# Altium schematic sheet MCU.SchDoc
size A
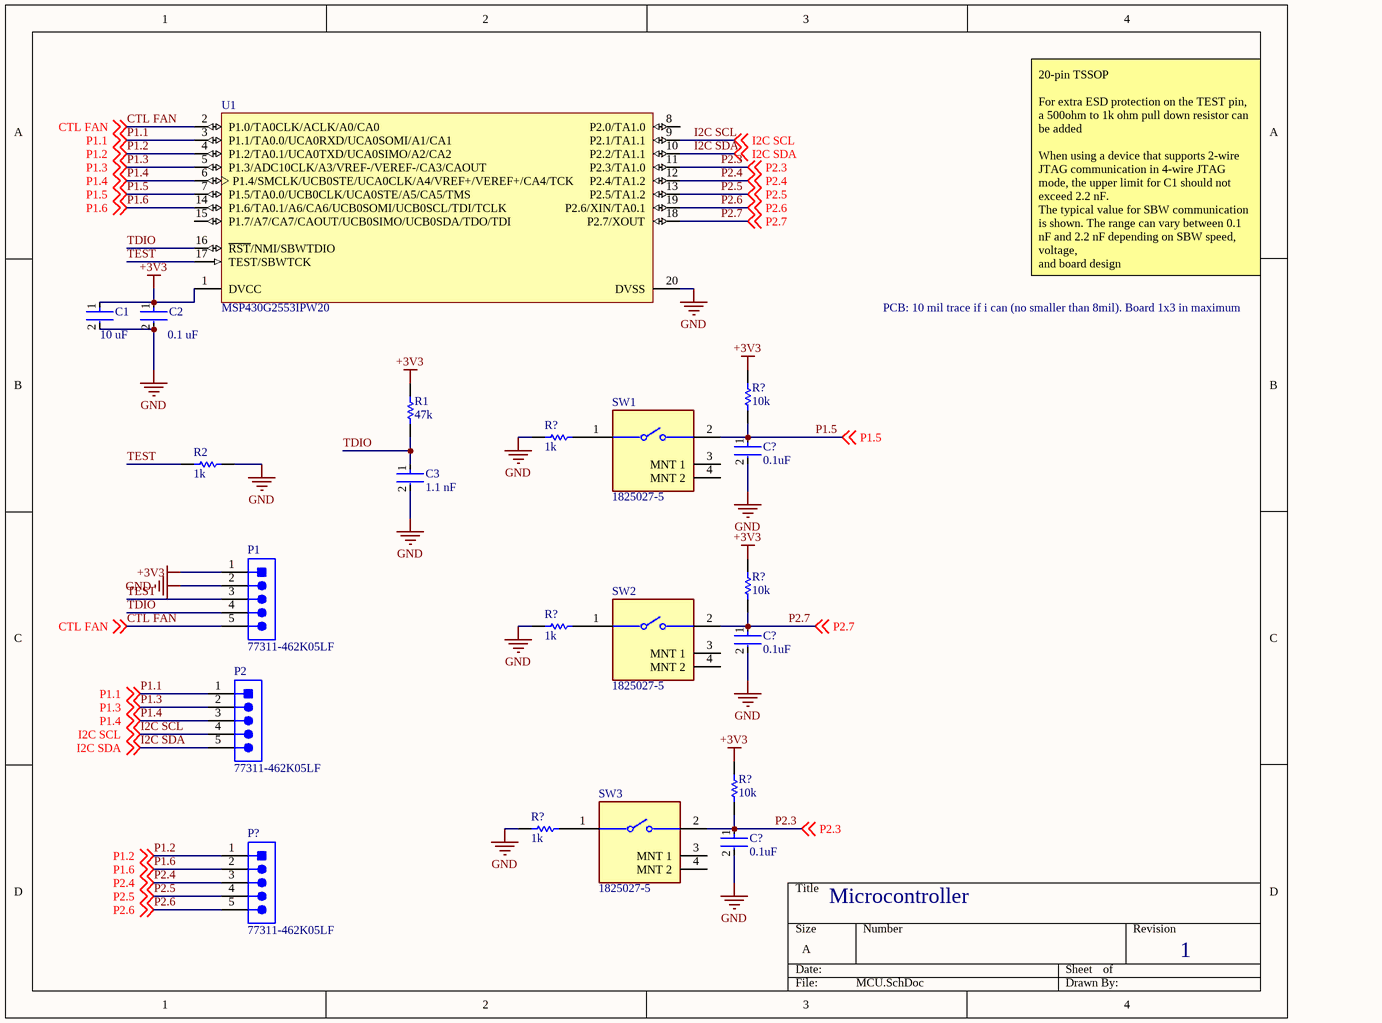
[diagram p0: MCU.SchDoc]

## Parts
(Parts that share a designator on the sheet are numbered #1, #2 ... from top to bottom, then left to right.)
C1  10 uF  [FP-C0805C-DG-MFG]
C2  0.1 uF  [FP-C0805C-DG-MFG]
C3  1.1 nF  [FP-C0805C-DG-MFG]
C?#1  0.1uF  [FP-C0805C-DG-MFG]
C?#2  0.1uF  [FP-C0805C-DG-MFG]
C?#3  0.1uF  [FP-C0805C-DG-MFG]
P1  77311-462K05LF  [FCI-77311-5_V]
P2  77311-462K05LF  [FCI-77311-5_V]
P?  77311-462K05LF  [FCI-77311-5_V]
R1  47k  [RESC2013X50X30LL20T20]
R2  1k  [RESC2013X50X30LL20T20]
R?#1  value 10k  [RESC2013X70X40ML20T20]  (hidden comment: Resistor 1k +/-1% 0805 125 mW)
R?#2  value 1k  [RESC2013X70X40ML20T20]  (hidden comment: Resistor 1k +/-1% 0805 125 mW)
R?#3  value 10k  [RESC2013X70X40ML20T20]  (hidden comment: Resistor 1k +/-1% 0805 125 mW)
R?#4  value 1k  [RESC2013X70X40ML20T20]  (hidden comment: Resistor 1k +/-1% 0805 125 mW)
R?#5  value 10k  [RESC2013X70X40ML20T20]  (hidden comment: Resistor 1k +/-1% 0805 125 mW)
R?#6  value 1k  [RESC2013X70X40ML20T20]  (hidden comment: Resistor 1k +/-1% 0805 125 mW)
SW1  1825027-5  [FP-1825027-5-0]
SW2  1825027-5  [FP-1825027-5-0]
SW3  1825027-5  [FP-1825027-5-0]
U1  MSP430G2553IPW20  [PW0020A_L]

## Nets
+3V3: C1.1 C2.1 P1.1(DTR) R1.2 R?#1.1 R?#3.1 R?#5.1 U1.1(DVCC)
GND: C1.2 C2.2 C3.2 C?#1.2 C?#2.2 C?#3.2 P1.2(RXI) R2.2 R?#2.2 R?#4.2 R?#6.2 U1.20(DVSS)
CTL FAN: P1.5(CTS) U1.2(P1.0/TA0CLK/ACLK/A0/CA0) ; off-sheet CTL FAN
I2C SCL: P2.4(VCC) U1.9(P2.1/TA1.1) ; off-sheet I2C SCL
I2C SDA: P2.5(CTS) U1.10(P2.2/TA1.1) ; off-sheet I2C SDA
P1.1: P2.1(DTR) U1.3(P1.1/TA0.0/UCA0RXD/UCA0SOMI/A1/CA1) ; off-sheet P1.1
P1.2: P?.1(DTR) U1.4(P1.2/TA0.1/UCA0TXD/UCA0SIMO/A2/CA2) ; off-sheet P1.2
P1.3: P2.2(RXI) U1.5(P1.3/ADC10CLK/A3/VREF-/VEREF-/CA3/CAOUT) ; off-sheet P1.3
P1.4: P2.3(TXO) U1.6(P1.4/SMCLK/UCB0STE/UCA0CLK/A4/VREF+/VEREF+/CA4/TCK) ; off-sheet P1.4
P1.5: C?#1.1 R?#1.2 SW1.2 U1.7(P1.5/TA0.0/UCB0CLK/UCA0STE/A5/CA5/TMS) ; off-sheet P1.5
P1.6: P?.2(RXI) U1.14(P1.6/TA0.1/A6/CA6/UCB0SOMI/UCB0SCL/TDI/TCLK) ; off-sheet P1.6
P2.3: C?#3.1 R?#5.2 SW3.2 U1.11(P2.3/TA1.0) ; off-sheet P2.3
P2.4: P?.3(TXO) U1.12(P2.4/TA1.2) ; off-sheet P2.4
P2.5: P?.4(VCC) U1.13(P2.5/TA1.2) ; off-sheet P2.5
P2.6: P?.5(CTS) U1.19(P2.6/XIN/TA0.1) ; off-sheet P2.6
P2.7: C?#2.1 R?#3.2 SW2.2 U1.18(P2.7/XOUT) ; off-sheet P2.7
TDIO: C3.1 P1.4(VCC) R1.1 U1.16(~{RST}/NMI/SBWTDIO)
TEST: P1.3(TXO) R2.1 U1.17(TEST/SBWTCK)
NetR?#2_1: R?#2.1 SW1.1
NetR?#4_1: R?#4.1 SW2.1
NetR?#6_1: R?#6.1 SW3.1

Not connected (* = marked no-connect by the designer): SW1 3(MNT_1) 4(MNT_2); SW2 3(MNT_1) 4(MNT_2); SW3 3(MNT_1) 4(MNT_2); U1 8(P2.0/TA1.0) 15(P1.7/A7/CA7/CAOUT/UCB0SIMO/UCB0SDA/TDO/TDI)

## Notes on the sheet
- 20-pin TSSOP
  For extra ESD protection on the TEST pin, a 500ohm to 1k ohm pull down resistor can be added
  When using a device that supports 2-wire JTAG communication in 4-wire JTAG mode, the upper limit for C1 should not exceed 2.2 nF.
  The typical value for SBW communication is shown. The range can vary between 0.1 nF and 2.2 nF depending on SBW speed, voltage,
  and board design
- PCB: 10 mil trace if i can (no smaller than 8mil). Board 1x3 in maximum
- Microcontroller
- 1

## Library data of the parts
C1-C3 C?#1-C?#3 = CMP-2007-03243-2: CAP CER 10UF 10V X5R 0805; Manufacturer Part Number: C0805C106K8PACTU; Manufacturer: Kemet; 3DS Part Number: 220-00001; Tolerance: 10%; Temperature Coefficient: 15%; Material: Ceramic
P1 P2 P? = CMP-1698-00006-1: Male Header, Pitch 2.54 mm, 1 x 5 Position, Height 16.24 mm, Tail Length 3.05 mm, / -65 to 125 degC, RoHS, Tape and Reel; Shielding: Shielded; Current Rating: 1 A; Gender: Female
R1 R2 = CMP-2001-04896-1: Manufacturer: Vishay Dale; Part Number: CRCW08050000Z0EA
R?#1-R?#6 = CMP-009-00010-4: Chip Resistor, 1 KOhm, +/- 1%, 0.125 W, -55 to 155 degC, 0805 (2013 Metric); Power: 125mW; Voltage Rating: 150V
SW1-SW3 = CMP-2000-05514-2: SWITCH TACTILE SPST-NO 0.05A 24V; Manufacturer: TE Connectivity; Contact Current Rating: 50mA; Contact Resistance: 100mΩ; Electromechanical Life: 100000Cycles; Operating Force: 160gf
U1 = CMP-0365-00585-2: 16 MHz Mixed Signal Microcontroller with 16 KB Flash, 512 B SRAM and 24 GPIOs, -40 to 85 degC, 20-pin SOP (PW), Green (RoHS & no Sb/Br); Manufacturer: Texas Instruments; Timers - 16-bit: 2; Temp Sensor: Yes; USCI_B (I2C & SPI): 1; SRAM(B): 512; ADC: 10-bit SAR; Frequency(MHz): 16; SubFamily: Value Line; ADC Channels: 8; GPIO: 24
